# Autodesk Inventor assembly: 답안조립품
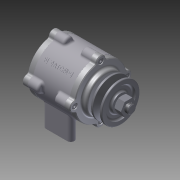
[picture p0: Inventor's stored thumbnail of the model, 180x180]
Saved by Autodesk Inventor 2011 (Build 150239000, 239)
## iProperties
Created: 2015-03
Part Number: 답안조립품
Document SubType Name: Assembly
Designer: Administrator
Author: Administrator
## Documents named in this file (11)
- C:\Documents and Settings\Administrator\바탕 화면\450305V1007\답안조립품.iam
- C:\Documents and Settings\Administrator\바탕 화면\450305V1007\본체.ipt
- C:\Documents and Settings\Administrator\바탕 화면\450305V1007\커버.ipt
- C:\Documents and Settings\Administrator\바탕 화면\450305V1007\M 4 x 12.ipt
- C:\Documents and Settings\Administrator\바탕 화면\450305V1007\커버2.ipt
- C:\Documents and Settings\Administrator\바탕 화면\450305V1007\베어링 6204.ipt
- C:\Documents and Settings\Administrator\바탕 화면\450305V1007\축.ipt
- C:\Documents and Settings\Administrator\바탕 화면\450305V1007\키(4 x 4 x 12).ipt
- C:\Documents and Settings\Administrator\바탕 화면\450305V1007\너트 M12x1.25.ipt
- C:\Documents and Settings\Administrator\바탕 화면\450305V1007\V벨트풀리.ipt
- C:\Documents and Settings\Administrator\바탕 화면\450305V1007\오일실.ipt
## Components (14 placed, 6 different names)
1. KS B 2023 6204 - 20 x 47 x 14:1
2. KS B 2023 6204 - 20 x 47 x 14:2
3. KS B 1311 (I) 4 x 4 x 12:1
4. KS B 1012 클래스 1 일반 - 미터 M12x1.25:1 — 각도:1
5. 그루브 풀리1:1
6. KS B 2804 D D - 20 32 8:1
7. KS B 1003 - 미터 M 4 x 12:1
8. KS B 1003 - 미터 M 4 x 12:2
9. KS B 1003 - 미터 M 4 x 12:3
10. KS B 1003 - 미터 M 4 x 12:4
11. KS B 1003 - 미터 M 4 x 12:5
12. KS B 1003 - 미터 M 4 x 12:6
13. KS B 1003 - 미터 M 4 x 12:7
14. KS B 1003 - 미터 M 4 x 12:8
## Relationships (1: Angle 1)
- 각도:1 [Angle]: KS B 1012 클래스 1 일반 - 미터 M12x1.25:1
